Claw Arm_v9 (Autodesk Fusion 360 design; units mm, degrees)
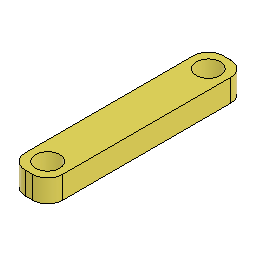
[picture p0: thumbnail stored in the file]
sketch "Sketch1" plane through (0, 0, 0) normal (0, 0, 1) x axis (1, 0, 0)
  line L1 (-2.5, -13.2385) -> (2.5, -13.2385)
  line L2 (-2.5, 13.2385) -> (-2.5, -13.2385)
  line L3 (2.5, 13.2385) -> (-2.5, 13.2385)
  line L4 (2.5, -13.2385) -> (2.5, 13.2385)
  line L5 (-2.5, 13.2385) -> (2.5, -13.2385)
  line L6 (2.5, 13.2385) -> (-2.5, -13.2385)
  line L7 (2.5, 0) -> (-2.5, 0)
  point P6 (0, 0)
  point P1 (0, 0)
  point P7 (-2.5, 0)
  point P8 (2.5, 0)
  point P4 (-2.5, 13.2385)
  point P5 (2.5, 13.2385)
  point P3 (-2.5, -13.2385)
  horizontal L1
  perpendicular L1 L2
  parallel L1 L3
  parallel L2 L4
  coincident L5 P6
  coincident L6 P6
  coincident P1 P6
  midpoint L2 P7
  midpoint L4 P8
  dimension "d1" distance P4 P5 = 5
  dimension "d2" distance P3 P4 = 26.477 (= "25 mm + 1.477 mm")
extrude "Extrude1" new body sketch "Sketch1" + "Sketch2" profile of S1:L1 S1:L2 S1:L3 S1:L4 blind 3
sketch "Sketch2" plane through (0, 0, 3) normal (0, 0, 1) x axis (-1, 0, 0)
  line L1 (2.5, -13.2385) -> (-2.5, -13.2385)
  line L2 (2.5, 13.2385) -> (2.5, -13.2385)
  line L3 (-2.5, 13.2385) -> (2.5, 13.2385)
  line L4 (-2.5, -13.2385) -> (-2.5, 13.2385)
  circle C1 centre (0, -10.7385) radius 1.6
  point P6 (0, -10.7385)
  dimension "d13" diameter C1 = 3.2
  dimension "d14" distance L1 P6 = 2.5
extrude "Extrude2" cut sketch "Sketch2" profile of C1 against normal blind 3
mirror "Mirror1" sketch "Sketch2" mirrorStitchTolerance 0.1
fillet "Fillet1" radius 2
